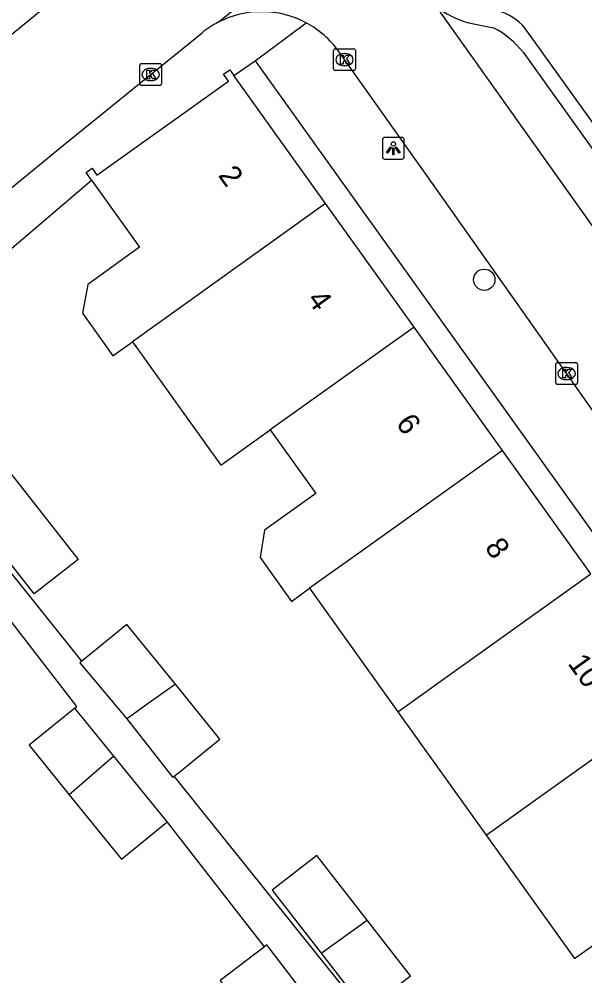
# Model space of a CAD drawing. Extents: x 162532 to 163264, y 381233 to 382042.
# Drawn here: x 162674.35 to 162700.32, y 381814.16 to 381858.1 of the extents above; entities that cross this region are included whole.
import ezdxf

# ---------------------------------------------------------------- set-up
doc = ezdxf.new("R2010")
doc.units = 0
for name, color, linetype in [('IMGEO_Boom', 7, 'Continuous'), ('IMGEO_Kolk', 7, 'Continuous'), ('IMGEO_Lichtpunt', 7, 'Continuous'), ('IMGEO_Muur', 7, 'Continuous'), ('IMGEO_Pand', 7, 'Continuous'), ('IMGEO_Pand_nummerreeks', 7, 'Continuous'), ('IMGEO_Rijbaan_lokaal_open', 7, 'Continuous'), ('IMGEO_Voetpad_open', 7, 'Continuous')]:
    doc.layers.add(name, color=color, linetype=linetype)

msp = doc.modelspace()

# ---------------------------------------------------------------- linework, layer by layer
at = {"layer": 'IMGEO_Boom'}
msp.add_circle((162695.702, 381846.129), 0.489, dxfattribs=at)
at = {"layer": 'IMGEO_Kolk'}
for p, q in [((162688.861, 381856.738), (162689.713, 381856.738)), ((162688.786, 381855.812), (162688.786, 381856.664)), ((162689.274, 381856.518), (162689.299, 381856.518)), ((162689.787, 381856.664), (162689.787, 381855.812)), ((162679.884, 381855.129), (162679.884, 381855.981)), ((162679.959, 381856.055), (162680.811, 381856.055)), ((162680.372, 381855.835), (162680.397, 381855.835)), ((162680.885, 381855.981), (162680.885, 381855.129)), ((162689.297, 381855.958), (162689.272, 381855.958)), ((162689.713, 381855.738), (162688.861, 381855.738)), ((162680.811, 381855.055), (162679.959, 381855.055)), ((162680.395, 381855.275), (162680.37, 381855.275)), ((162698.982, 381841.396), (162698.982, 381842.248)), ((162699.057, 381842.322), (162699.909, 381842.322)), ((162699.983, 381842.248), (162699.983, 381841.396)), ((162699.47, 381842.102), (162699.495, 381842.102)), ((162699.909, 381841.322), (162699.057, 381841.322)), ((162699.493, 381841.542), (162699.468, 381841.542))]:
    msp.add_line(p, q, dxfattribs=at)
for points in [[(162688.861, 381856.738), (162689.713, 381856.738)], [(162688.786, 381855.812), (162688.786, 381856.664)], [(162689.107, 381856.438), (162689.23, 381856.438), (162689.23, 381856.287), (162689.36, 381856.438), (162689.524, 381856.438), (162689.378, 381856.287), (162689.531, 381856.038), (162689.379, 381856.038), (162689.294, 381856.202), (162689.23, 381856.135), (162689.23, 381856.038), (162689.107, 381856.038), (162689.107, 381856.438)], [(162689.787, 381856.664), (162689.787, 381855.812)], [(162679.884, 381855.129), (162679.884, 381855.981)], [(162679.959, 381856.055), (162680.811, 381856.055)], [(162680.885, 381855.981), (162680.885, 381855.129)], [(162680.205, 381855.755), (162680.328, 381855.755), (162680.328, 381855.604), (162680.458, 381855.755), (162680.622, 381855.755), (162680.476, 381855.604), (162680.629, 381855.355), (162680.477, 381855.355), (162680.392, 381855.519), (162680.328, 381855.452), (162680.328, 381855.355), (162680.205, 381855.355), (162680.205, 381855.755)], [(162689.713, 381855.738), (162688.861, 381855.738)], [(162680.811, 381855.055), (162679.959, 381855.055)], [(162698.982, 381841.396), (162698.982, 381842.248)], [(162699.057, 381842.322), (162699.909, 381842.322)], [(162699.983, 381842.248), (162699.983, 381841.396)], [(162699.303, 381842.022), (162699.426, 381842.022), (162699.426, 381841.871), (162699.556, 381842.022), (162699.72, 381842.022), (162699.574, 381841.871), (162699.727, 381841.622), (162699.575, 381841.622), (162699.49, 381841.786), (162699.426, 381841.719), (162699.426, 381841.622), (162699.303, 381841.622), (162699.303, 381842.022)], [(162699.909, 381841.322), (162699.057, 381841.322)]]:
    msp.add_lwpolyline(points, dxfattribs=at)
for centre, start, end in [((162688.863, 381856.662), 91.552, 178.448), ((162688.863, 381856.662), 91.552, 178.448), ((162689.711, 381856.662), 1.552, 88.448), ((162689.711, 381856.662), 1.552, 88.448), ((162679.961, 381855.979), 91.552, 178.448), ((162679.961, 381855.979), 91.552, 178.448), ((162680.809, 381855.979), 1.552, 88.448), ((162680.809, 381855.979), 1.552, 88.448), ((162688.863, 381855.814), 181.552, 268.448), ((162688.863, 381855.814), 181.552, 268.448), ((162689.711, 381855.814), 271.552, 358.448), ((162689.711, 381855.814), 271.552, 358.448), ((162679.961, 381855.131), 181.552, 268.448), ((162679.961, 381855.131), 181.552, 268.448), ((162680.809, 381855.131), 271.552, 358.448), ((162680.809, 381855.131), 271.552, 358.448), ((162699.059, 381842.246), 91.552, 178.448), ((162699.059, 381842.246), 91.552, 178.448), ((162699.907, 381842.246), 1.552, 88.448), ((162699.907, 381842.246), 1.552, 88.448), ((162699.059, 381841.398), 181.552, 268.448), ((162699.059, 381841.398), 181.552, 268.448), ((162699.907, 381841.398), 271.552, 358.448), ((162699.907, 381841.398), 271.552, 358.448)]:
    msp.add_arc(centre, 0.0765, start, end, dxfattribs=at)
for centre, major_axis, ratio, start_param, end_param in [((162689.273, 381856.238), (-0.387, 0.002), 0.722429, 4.712389, 7.853982), ((162689.298, 381856.238), (-0.39, 0.002), 0.717154, 1.570796, 4.712389), ((162680.371, 381855.555), (-0.387, 0.002), 0.722429, 4.712389, 7.853982), ((162680.396, 381855.555), (-0.39, 0.002), 0.717154, 1.570796, 4.712389), ((162699.469, 381841.822), (-0.387, 0.002), 0.722429, 4.712389, 7.853982), ((162699.494, 381841.822), (-0.39, 0.002), 0.717154, 1.570796, 4.712389)]:
    msp.add_ellipse(centre, major_axis=major_axis, ratio=ratio, start_param=start_param, end_param=end_param, dxfattribs=at)
at = {"layer": 'IMGEO_Lichtpunt'}
for p, q in [((162691.03, 381852.571), (162691.03, 381851.764)), ((162691.03, 381852.571), (162691.03, 381851.764)), ((162691.932, 381852.666), (162691.124, 381852.666)), ((162691.932, 381852.666), (162691.124, 381852.666)), ((162692.026, 381851.764), (162692.026, 381852.571)), ((162692.026, 381851.764), (162692.026, 381852.571)), ((162691.124, 381851.67), (162691.932, 381851.67)), ((162691.124, 381851.67), (162691.932, 381851.67))]:
    msp.add_line(p, q, dxfattribs=at)
for points in [[(162691.404, 381852.235), (162691.443, 381852.207), (162691.255, 381851.945), (162691.217, 381851.972), (162691.404, 381852.235)], [(162691.506, 381852.187), (162691.553, 381852.187), (162691.553, 381851.865), (162691.506, 381851.865), (162691.506, 381852.187)], [(162691.616, 381852.207), (162691.654, 381852.234), (162691.841, 381851.972), (162691.802, 381851.944), (162691.616, 381852.207)]]:
    msp.add_lwpolyline(points, dxfattribs=at)
msp.add_circle((162691.529, 381852.369), 0.0994, dxfattribs=at)
for centre, start, end in [((162691.124, 381852.571), 90, 180), ((162691.124, 381852.571), 90, 180), ((162691.932, 381852.571), 0, 90), ((162691.932, 381852.571), 0, 90), ((162691.124, 381851.764), 180, 270), ((162691.124, 381851.764), 180, 270), ((162691.932, 381851.764), 270, 0), ((162691.932, 381851.764), 270, 360)]:
    msp.add_arc(centre, 0.0946, start, end, dxfattribs=at)
at = {"layer": 'IMGEO_Muur'}
msp.add_lwpolyline([(162669.496, 381843.741), (162677.677, 381850.696)], dxfattribs=at)
at = {"layer": 'IMGEO_Pand'}
for points in [[(162677.677, 381850.696), (162677.421, 381851.053), (162677.693, 381851.248), (162677.922, 381850.928), (162683.96, 381855.25), (162683.733, 381855.567), (162684.019, 381855.771), (162684.204, 381855.513)], [(162688.419, 381849.626), (162684.204, 381855.513)], [(162677.677, 381850.696), (162679.88, 381847.619), (162677.497, 381845.913), (162677.25, 381844.593), (162678.653, 381842.633), (162679.56, 381843.284)], [(162688.419, 381849.626), (162681.822, 381844.906), (162679.56, 381843.284)], [(162692.477, 381843.958), (162688.419, 381849.626)], [(162692.477, 381843.958), (162685.879, 381839.239)], [(162696.534, 381838.291), (162692.477, 381843.958)], [(162679.56, 381843.284), (162683.615, 381837.62), (162685.879, 381839.239)], [(162685.879, 381839.239), (162687.975, 381836.312), (162685.617, 381834.624), (162685.409, 381833.368), (162686.847, 381831.36), (162687.682, 381831.958)], [(162672.885, 381838.589), (162677.055, 381833.283), (162675.044, 381831.702), (162670.918, 381836.951)], [(162696.534, 381838.291), (162689.937, 381833.572), (162687.682, 381831.958)], [(162700.591, 381832.623), (162696.534, 381838.291)], [(162691.739, 381826.291), (162693.994, 381827.904), (162700.591, 381832.623)], [(162687.682, 381831.958), (162691.739, 381826.291)], [(162681.522, 381827.552), (162679.298, 381830.294), (162677.229, 381828.616)], [(162677.229, 381828.616), (162677.13, 381828.535), (162679.299, 381825.961)], [(162681.522, 381827.552), (162681.414, 381827.475), (162680.17, 381826.585), (162679.595, 381826.173), (162679.299, 381825.961)], [(162681.469, 381823.324), (162681.663, 381823.482), (162683.569, 381825.029), (162681.522, 381827.552)], [(162695.795, 381820.623), (162698.052, 381822.237), (162704.649, 381826.956)], [(162676.905, 381826.459), (162674.802, 381824.753), (162676.652, 381822.473)], [(162678.696, 381824.251), (162676.905, 381826.459)], [(162679.299, 381825.961), (162681.402, 381823.27), (162681.45, 381823.309), (162681.469, 381823.324)], [(162691.739, 381826.291), (162695.795, 381820.623)], [(162678.696, 381824.251), (162676.652, 381822.473)], [(162681.155, 381821.22), (162678.696, 381824.251)], [(162676.652, 381822.473), (162678.957, 381819.631), (162679.054, 381819.512), (162681.059, 381821.151), (162681.155, 381821.22)], [(162695.795, 381820.623), (162699.851, 381814.955), (162702.109, 381816.57)], [(162690.328, 381816.713), (162688.017, 381819.691), (162685.962, 381818.097), (162688.211, 381815.198)], [(162688.211, 381815.198), (162690.328, 381816.713)], [(162688.211, 381815.198), (162690.254, 381812.565), (162692.309, 381814.16), (162690.328, 381816.713)], [(162685.615, 381815.497), (162683.576, 381813.944), (162683.709, 381813.768), (162685.374, 381811.583)], [(162687.415, 381813.36), (162685.857, 381815.405), (162685.724, 381815.58), (162685.615, 381815.497)]]:
    msp.add_lwpolyline(points, dxfattribs=at)
at = {"layer": 'IMGEO_Rijbaan_lokaal_open'}
for points in [[(162694.996, 381874.59), (162688.855, 381869.619), (162681.316, 381863.363), (162672.848, 381856.46), (162665.027, 381850.088), (162661.191, 381846.959)], [(162683.487, 381857.957), (162693.54, 381865.99)], [(162740.722, 381792.594), (162728.313, 381810.023), (162715.566, 381827.76), (162703.613, 381844.475), (162693.495, 381858.692)], [(162668.127, 381845.543), (162676.395, 381852.319), (162682.745, 381857.472)], [(162740.416, 381785.225), (162737.359, 381788.833), (162729.638, 381799.644), (162719.288, 381814.036), (162703.538, 381836.077), (162693.329, 381850.547), (162689.021, 381856.614)]]:
    msp.add_lwpolyline(points, dxfattribs=at)
for centre, radius, start, end in [((162685.482, 381854.097), 4.345, 62.0182, 117.3283), ((162685.403, 381854.216), 4.203, 117.1169, 129.2235), ((162685.462, 381854.08), 4.369, 35.4471, 61.8952)]:
    msp.add_arc(centre, radius, start, end, dxfattribs=at)
at = {"layer": 'IMGEO_Voetpad_open'}
for points in [[(162685.191, 381856.189), (162687.52, 381857.934)], [(162694.921, 381857.95), (162696.126, 381857.706)], [(162711.041, 381838.922), (162697.58, 381857.674)], [(162697.482, 381856.586), (162740.249, 381796.81)], [(162684.204, 381855.513), (162685.191, 381856.189)], [(162685.191, 381856.189), (162733.516, 381788.621)], [(162669.496, 381843.741), (162677.677, 381850.696)], [(162677.229, 381828.616), (162666.869, 381841.547)], [(162676.905, 381826.459), (162676.992, 381826.53), (162673.894, 381830.556)], [(162694.58, 381806.781), (162690.152, 381812.486), (162681.469, 381823.324)], [(162685.615, 381815.497), (162681.155, 381821.22)]]:
    msp.add_lwpolyline(points, dxfattribs=at)
for centre, radius, start, end in [((162696.031, 381861.825), 4.031, 231.0081, 254.0127), ((162695.822, 381856.281), 2.243, 38.4031, 77.203), ((162694.166, 381853.952), 4.234, 38.459, 62.4304)]:
    msp.add_arc(centre, radius, start, end, dxfattribs=at)

# ---------------------------------------------------------------- texts
at = {"layer": 'IMGEO_Pand_nummerreeks'}
for s, p in [('2', (162683.456, 381850.922)), ('4', (162687.535, 381845.223)), ('6', (162691.614, 381839.527)), ('8', (162695.695, 381833.827)), ('10', (162699.505, 381828.506))]:
    msp.add_text(s, height=1, rotation=305.6034, dxfattribs=at).set_placement(p)

doc.saveas('drawing.dxf')
